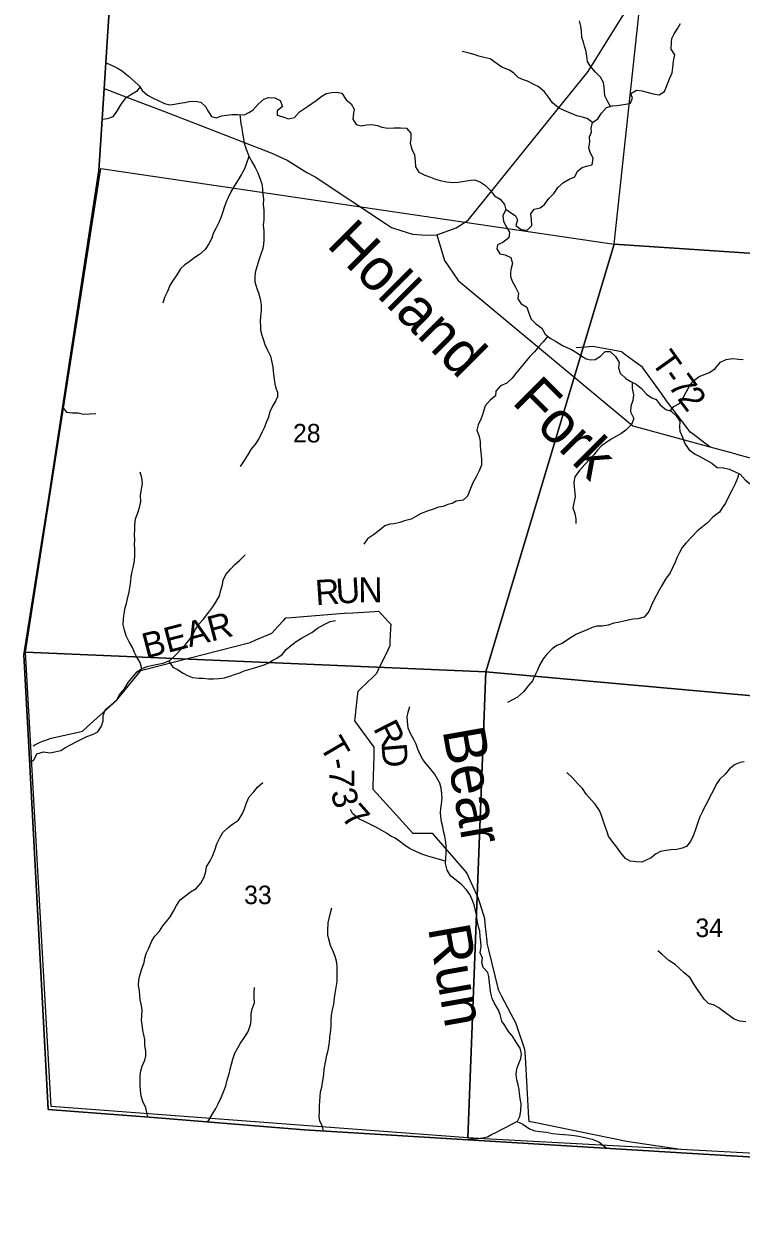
# Model space of a CAD drawing. Extents: x 1715311 to 2083412, y 146837 to 553079.
# Drawn here: x 1893959 to 1902515, y 310262 to 324418 of the extents above; entities that cross this region are included whole.
import ezdxf

# ---------------------------------------------------------------- set-up
doc = ezdxf.new("R2010")
doc.units = 0
for name, color, linetype in [('GM_X_Adjacent_County', 7, 'Continuous'), ('GM_X_County', 7, 'Continuous'), ('GM_X_Minor_River', 7, 'Continuous'), ('GM_X_Minor_River_Text', 7, 'Continuous'), ('GM_X_Section', 7, 'Continuous'), ('GM_X_Section_Text', 7, 'Continuous'), ('GM_X_State_Route', 7, 'Continuous'), ('GM_X_Township', 7, 'Continuous'), ('GM_X_Township_Road', 7, 'Continuous'), ('GM_X_Township_Road_Text', 7, 'Continuous')]:
    doc.layers.add(name, color=color, linetype=linetype)

msp = doc.modelspace()

# ---------------------------------------------------------------- linework, layer by layer
at = {"layer": 'GM_X_Adjacent_County'}
msp.add_lwpolyline([(1896008, 339458), (1895779, 336659), (1895744, 336194), (1895699, 335683), (1895663, 335244), (1895523, 333111), (1895188, 327845), (1894919, 323647), (1894856, 322668), (1894263, 318800), (1893959, 316894), (1894019, 315798), (1894252, 311474), (1895508, 311379), (1897304, 311233), (1901800, 310959), (1903135, 310878), (1905084, 310759), (1910567, 310425), (1912652, 310262)], dxfattribs=at)
at = {"layer": 'GM_X_County'}
msp.add_lwpolyline([(1912652, 310262), (1910567, 310425), (1905084, 310759), (1903135, 310878), (1901800, 310959), (1897304, 311233), (1895508, 311379), (1894252, 311474), (1894019, 315798), (1893959, 316894), (1894263, 318800), (1894856, 322668), (1894919, 323647), (1895188, 327845), (1895523, 333111), (1895663, 335244), (1895699, 335683), (1895744, 336194), (1895779, 336659), (1896008, 339458)], dxfattribs=at)
at = {"layer": 'GM_X_Minor_River'}
for points in [[(1900957, 323433), (1900924, 323486), (1900888, 323558), (1900886, 323610), (1900880, 323662), (1900871, 323716), (1900837, 323783), (1900777, 323839), (1900713, 323917), (1900682, 323967), (1900672, 324031), (1900664, 324088), (1900644, 324150), (1900633, 324200), (1900615, 324252), (1900609, 324330), (1900603, 324388), (1900588, 324452)], [(1899706, 322208), (1899748, 322178), (1899822, 322129), (1899846, 322079), (1899828, 322011), (1899891, 321967), (1899963, 321957), (1900017, 322011), (1900014, 322085), (1900004, 322153), (1900044, 322209), (1900118, 322224), (1900168, 322264), (1900222, 322336), (1900284, 322400), (1900327, 322464), (1900395, 322527), (1900463, 322565), (1900529, 322595), (1900563, 322659), (1900617, 322705), (1900669, 322721), (1900737, 322736), (1900751, 322816), (1900714, 322883), (1900698, 322939), (1900710, 323005), (1900704, 323069), (1900731, 323125), (1900725, 323175), (1900743, 323241), (1900805, 323286), (1900847, 323350), (1900907, 323418), (1900979, 323440), (1901031, 323442), (1901087, 323451), (1901139, 323459), (1901195, 323473), (1901217, 323531), (1901198, 323585), (1901264, 323627), (1901332, 323619), (1901389, 323602), (1901465, 323582), (1901535, 323570), (1901601, 323610), (1901633, 323688), (1901658, 323760), (1901690, 323831), (1901698, 323895), (1901708, 323973), (1901721, 324049), (1901681, 324116), (1901685, 324194), (1901689, 324244), (1901716, 324296), (1901758, 324366), (1901790, 324419)], [(1900743, 323240), (1900677, 323287), (1900607, 323309), (1900555, 323321), (1900478, 323352), (1900402, 323382), (1900334, 323414), (1900264, 323475), (1900217, 323543), (1900167, 323605), (1900095, 323669), (1900042, 323694), (1899968, 323732), (1899908, 323754), (1899856, 323778), (1899802, 323827), (1899751, 323863), (1899661, 323899), (1899593, 323948), (1899521, 323998), (1899449, 324014), (1899386, 324032), (1899330, 324053), (1899254, 324073), (1899188, 324087)], [(1894942, 323953), (1895023, 323917), (1895085, 323883), (1895137, 323853), (1895209, 323793), (1895276, 323732), (1895340, 323674), (1895370, 323622), (1895434, 323568), (1895504, 323529), (1895555, 323505), (1895639, 323469), (1895701, 323453), (1895757, 323458), (1895819, 323470), (1895875, 323480), (1895933, 323490), (1896003, 323496), (1896071, 323485), (1896125, 323433), (1896162, 323367), (1896198, 323313), (1896252, 323295), (1896322, 323320), (1896378, 323330), (1896442, 323336), (1896510, 323338), (1896590, 323331), (1896644, 323361), (1896694, 323393), (1896756, 323459), (1896824, 323519), (1896877, 323537), (1896952, 323536), (1897016, 323504), (1897046, 323432), (1896980, 323380), (1896982, 323330), (1897050, 323310), (1897117, 323286), (1897189, 323301), (1897246, 323369), (1897342, 323430)], [(1895346, 323664), (1895302, 323612), (1895236, 323570), (1895166, 323523), (1895112, 323453), (1895073, 323383), (1895021, 323309), (1894953, 323283), (1894899, 323277)], [(1897342, 323430), (1897446, 323504), (1897512, 323555), (1897564, 323587), (1897634, 323599), (1897688, 323601), (1897754, 323592), (1897802, 323512), (1897863, 323464), (1897901, 323400), (1897893, 323350), (1897885, 323282), (1897924, 323217), (1897982, 323199), (1898046, 323211), (1898108, 323217), (1898176, 323204), (1898228, 323184), (1898302, 323172), (1898378, 323178), (1898452, 323179), (1898522, 323175), (1898573, 323115), (1898575, 323047), (1898569, 322995), (1898587, 322921), (1898618, 322857), (1898628, 322780), (1898630, 322712), (1898671, 322648), (1898743, 322612), (1898809, 322588), (1898869, 322565), (1898925, 322549), (1898999, 322535), (1899076, 322525), (1899140, 322528), (1899216, 322542), (1899286, 322554), (1899340, 322558), (1899406, 322531), (1899464, 322489), (1899524, 322431), (1899573, 322365), (1899639, 322326), (1899693, 322264), (1899708, 322200), (1899670, 322134), (1899678, 322062), (1899714, 321994), (1899751, 321934), (1899745, 321866), (1899673, 321812), (1899609, 321784), (1899601, 321734), (1899635, 321674), (1899698, 321662), (1899766, 321631), (1899786, 321561), (1899772, 321505), (1899764, 321455), (1899765, 321403), (1899785, 321349), (1899821, 321277), (1899857, 321207), (1899850, 321137), (1899892, 321078), (1899958, 321040), (1899980, 320968), (1900011, 320896), (1900067, 320842), (1900137, 320789), (1900176, 320719), (1900238, 320671), (1900300, 320635), (1900384, 320584), (1900435, 320560), (1900491, 320536), (1900561, 320491), (1900613, 320455), (1900667, 320423), (1900721, 320413), (1900774, 320417), (1900835, 320454), (1900893, 320512), (1900953, 320512), (1901016, 320452), (1901060, 320381), (1901050, 320317), (1901069, 320253), (1901137, 320191), (1901189, 320157), (1901263, 320120), (1901326, 320068), (1901384, 320004), (1901450, 319960), (1901502, 319937), (1901547, 319875), (1901615, 319819), (1901681, 319801), (1901739, 319746)], [(1896537, 323336), (1896548, 323225), (1896561, 323173), (1896569, 323109), (1896579, 323045), (1896589, 322993), (1896611, 322921), (1896638, 322851), (1896674, 322779), (1896718, 322706), (1896751, 322640), (1896779, 322566), (1896797, 322510), (1896807, 322446), (1896812, 322388), (1896818, 322328), (1896816, 322262), (1896822, 322194), (1896821, 322081), (1896815, 322015), (1896823, 321947), (1896823, 321841), (1896820, 321791), (1896810, 321739), (1896784, 321659), (1896758, 321589), (1896744, 321531), (1896723, 321467), (1896713, 321411), (1896713, 321341), (1896739, 321261), (1896758, 321211), (1896778, 321137), (1896790, 321069), (1896790, 320994), (1896783, 320934), (1896779, 320866), (1896781, 320814), (1896783, 320764), (1896799, 320706), (1896818, 320646), (1896834, 320596), (1896866, 320528), (1896900, 320456), (1896915, 320400), (1896929, 320329), (1896935, 320277), (1896947, 320177), (1896952, 320125), (1896966, 320075), (1896986, 320025), (1896984, 319969), (1896960, 319917), (1896925, 319861), (1896895, 319791), (1896875, 319717), (1896851, 319665), (1896831, 319609), (1896804, 319553), (1896766, 319479), (1896724, 319411), (1896668, 319341), (1896626, 319277), (1896587, 319212), (1896541, 319142)], [(1896645, 322837), (1896610, 322745), (1896590, 322689), (1896552, 322617), (1896515, 322559), (1896469, 322483), (1896425, 322405), (1896395, 322345), (1896370, 322285), (1896348, 322229), (1896332, 322175), (1896312, 322117), (1896286, 322047), (1896252, 321987), (1896219, 321919), (1896201, 321861), (1896165, 321793), (1896123, 321726), (1896055, 321666), (1895998, 321630), (1895932, 321580), (1895880, 321546), (1895828, 321496), (1895786, 321424), (1895734, 321351), (1895703, 321297), (1895675, 321227), (1895639, 321155), (1895617, 321089)], [(1900207, 320695), (1900154, 320627), (1900098, 320567), (1900048, 320507), (1899988, 320446), (1899933, 320378), (1899877, 320314), (1899835, 320262), (1899783, 320194), (1899719, 320132), (1899643, 320103), (1899589, 320037), (1899584, 319981), (1899520, 319929), (1899462, 319865), (1899444, 319813), (1899430, 319755), (1899410, 319703), (1899379, 319635), (1899363, 319573), (1899391, 319499), (1899403, 319437), (1899402, 319383), (1899408, 319305), (1899416, 319229), (1899416, 319157), (1899389, 319089), (1899355, 319017), (1899315, 318947), (1899285, 318879), (1899251, 318785)], [(1901666, 319805), (1901709, 319857), (1901777, 319892), (1901823, 319960), (1901862, 320034), (1901900, 320104), (1901948, 320166), (1902014, 320214), (1902086, 320239), (1902138, 320259), (1902202, 320307), (1902266, 320383), (1902334, 320417), (1902410, 320428), (1902484, 320420), (1902538, 320416)], [(1901213, 320145), (1901215, 320075), (1901230, 319994), (1901222, 319928), (1901200, 319860), (1901196, 319792), (1901235, 319712), (1901205, 319642), (1901139, 319573), (1901079, 319529), (1901027, 319503), (1900963, 319465), (1900899, 319421), (1900849, 319386), (1900796, 319332), (1900758, 319278), (1900708, 319226), (1900650, 319164), (1900586, 319094), (1900530, 319018), (1900519, 318952), (1900521, 318898), (1900535, 318783)], [(1894426, 319842), (1894469, 319789), (1894539, 319779), (1894607, 319781), (1894673, 319765), (1894743, 319768), (1894819, 319770)], [(1901739, 319746), (1901782, 319680), (1901780, 319610), (1901782, 319560), (1901810, 319496), (1901845, 319408), (1901893, 319337), (1901965, 319289), (1902021, 319261), (1902092, 319221), (1902162, 319180), (1902226, 319130), (1902302, 319124), (1902370, 319109), (1902435, 319079), (1902501, 319047), (1902561, 318981), (1902627, 318928), (1902678, 318898), (1902752, 318868), (1902818, 318850), (1902886, 318829), (1902987, 318778)], [(1895353, 318796), (1895365, 318869), (1895375, 318936), (1895368, 319006), (1895346, 319074)], [(1902486, 319054), (1902469, 319001), (1902443, 318933), (1902405, 318861), (1902363, 318779)], [(1895366, 316730), (1895349, 316805), (1895307, 316869), (1895279, 316921), (1895256, 316983), (1895216, 317050), (1895182, 317120), (1895160, 317188), (1895145, 317252), (1895147, 317324), (1895157, 317388), (1895169, 317454), (1895186, 317506), (1895198, 317562), (1895216, 317648), (1895230, 317718), (1895237, 317772), (1895241, 317822), (1895249, 317872), (1895265, 317938), (1895280, 318015), (1895286, 318085), (1895284, 318159), (1895282, 318211), (1895283, 318271), (1895281, 318321), (1895285, 318389), (1895285, 318441), (1895293, 318515), (1895318, 318587), (1895340, 318651), (1895355, 318723), (1895353, 318796)], [(1899251, 318785), (1899199, 318740), (1899116, 318725), (1899066, 318701), (1899016, 318686), (1898962, 318664), (1898906, 318654), (1898834, 318628), (1898782, 318612), (1898700, 318580), (1898636, 318545), (1898578, 318513), (1898500, 318493), (1898442, 318473), (1898376, 318457), (1898324, 318451), (1898266, 318434), (1898197, 318376), (1898131, 318326), (1898057, 318276), (1898013, 318216)], [(1900535, 318783), (1900507, 318649), (1900532, 318581), (1900544, 318515), (1900542, 318461)], [(1902363, 318779), (1902325, 318702), (1902289, 318646), (1902255, 318594), (1902177, 318536), (1902113, 318470), (1902053, 318420), (1901995, 318372), (1901924, 318300), (1901854, 318226), (1901812, 318173), (1901778, 318113), (1901752, 318059), (1901726, 318001), (1901691, 317925), (1901667, 317873), (1901611, 317797), (1901567, 317721), (1901537, 317665), (1901505, 317607), (1901476, 317553), (1901444, 317487), (1901412, 317413), (1901356, 317345), (1901282, 317325), (1901224, 317319), (1901168, 317308), (1901116, 317296), (1901048, 317280), (1900994, 317272), (1900926, 317250), (1900856, 317238), (1900792, 317235), (1900738, 317219), (1900684, 317199), (1900618, 317169), (1900552, 317141), (1900480, 317099), (1900380, 317032), (1900316, 317008), (1900260, 316968), (1900197, 316904), (1900151, 316848), (1900109, 316770), (1900087, 316714), (1900053, 316650), (1900027, 316584), (1899974, 316526), (1899918, 316456), (1899848, 316392), (1899786, 316359), (1899726, 316327)], [(1894032, 315615), (1894078, 315639), (1894116, 315713), (1894197, 315737), (1894271, 315728), (1894331, 315738), (1894401, 315756), (1894451, 315785), (1894525, 315825), (1894593, 315861), (1894649, 315889), (1894711, 315922), (1894779, 315944), (1894844, 315978), (1894888, 316046), (1894906, 316108), (1894906, 316172), (1894933, 316242), (1895001, 316298), (1895069, 316357), (1895105, 316431), (1895164, 316499), (1895206, 316565), (1895264, 316635), (1895312, 316693), (1895367, 316731), (1895433, 316756), (1895499, 316772), (1895579, 316786), (1895633, 316799), (1895707, 316833), (1895765, 316887), (1895836, 316961), (1895890, 317019), (1895944, 317086), (1895974, 317138), (1896009, 317196), (1896049, 317262), (1896099, 317318), (1896165, 317402), (1896216, 317468), (1896250, 317522), (1896292, 317598), (1896310, 317666), (1896331, 317732), (1896339, 317784), (1896369, 317853), (1896425, 317917), (1896472, 317969), (1896536, 318023), (1896600, 318087)], [(1897324, 317123), (1897396, 317163), (1897462, 317213), (1897542, 317258), (1897614, 317292), (1897676, 317304)], [(1895687, 316824), (1895739, 316747), (1895793, 316721), (1895860, 316678), (1895914, 316650), (1895970, 316624), (1896046, 316615), (1896098, 316615), (1896162, 316609), (1896224, 316609), (1896286, 316612), (1896354, 316622), (1896418, 316642), (1896483, 316664), (1896537, 316679), (1896589, 316703), (1896643, 316721), (1896699, 316735), (1896825, 316776), (1896877, 316800), (1896929, 316830), (1896979, 316856), (1897042, 316899), (1897088, 316959), (1897156, 317015), (1897208, 317053), (1897272, 317093), (1897324, 317123)], [(1899841, 311330), (1899875, 311393), (1899887, 311461), (1899889, 311541), (1899879, 311605), (1899871, 311665), (1899868, 311715), (1899856, 311771), (1899838, 311829), (1899830, 311893), (1899840, 311961), (1899861, 312025), (1899885, 312085), (1899895, 312135), (1899877, 312206), (1899829, 312278), (1899788, 312350), (1899740, 312404), (1899694, 312476), (1899662, 312527), (1899640, 312607), (1899619, 312661), (1899569, 312747), (1899545, 312799), (1899529, 312863), (1899522, 312919), (1899512, 312988), (1899504, 313060), (1899492, 313110), (1899436, 313166), (1899423, 313228), (1899429, 313278), (1899403, 313342), (1899415, 313420), (1899409, 313470), (1899402, 313536), (1899396, 313601), (1899382, 313653), (1899366, 313727), (1899358, 313795), (1899347, 313849), (1899329, 313915), (1899311, 313967), (1899279, 314037), (1899239, 314092), (1899184, 314154), (1899120, 314206), (1899052, 314258), (1899010, 314329), (1898989, 314407), (1898991, 314467), (1898997, 314537), (1898995, 314611), (1898993, 314661), (1898982, 314733), (1898964, 314793), (1898956, 314845), (1898942, 314903), (1898932, 314962), (1898930, 315014), (1898933, 315064), (1898941, 315116), (1898949, 315190), (1898943, 315240), (1898935, 315304), (1898920, 315364), (1898888, 315422), (1898856, 315476), (1898804, 315539), (1898756, 315595), (1898719, 315647), (1898689, 315701), (1898659, 315771), (1898637, 315829), (1898611, 315884), (1898572, 315958), (1898544, 316020), (1898534, 316106), (1898532, 316156), (1898542, 316210), (1898563, 316278)], [(1902550, 315621), (1902500, 315610), (1902442, 315586), (1902376, 315536), (1902321, 315472), (1902257, 315410), (1902221, 315358), (1902183, 315280), (1902137, 315196), (1902109, 315136), (1902078, 315080), (1902054, 315028), (1902022, 314964), (1902000, 314910), (1901982, 314850), (1901962, 314788), (1901943, 314736), (1901911, 314668), (1901863, 314610), (1901811, 314590), (1901747, 314575), (1901677, 314569), (1901621, 314563), (1901553, 314549), (1901491, 314517), (1901439, 314477), (1901389, 314452), (1901329, 314424), (1901261, 314426), (1901189, 314436), (1901135, 314468), (1901079, 314533), (1901032, 314603), (1900982, 314663), (1900932, 314735), (1900916, 314785), (1900893, 314847), (1900871, 314908), (1900849, 314980), (1900825, 315040), (1900771, 315116), (1900726, 315166), (1900666, 315235), (1900622, 315303), (1900572, 315355), (1900503, 315427), (1900435, 315494)], [(1895439, 311385), (1895416, 311494), (1895381, 311572), (1895359, 311636), (1895353, 311704), (1895349, 311761), (1895348, 311815), (1895348, 311879), (1895354, 311937), (1895370, 311993), (1895403, 312063), (1895415, 312115), (1895417, 312167), (1895405, 312241), (1895402, 312309), (1895390, 312367), (1895378, 312421), (1895370, 312489), (1895364, 312539), (1895367, 312591), (1895371, 312658), (1895365, 312714), (1895349, 312784), (1895342, 312834), (1895338, 312888), (1895328, 312954), (1895332, 313020), (1895343, 313072), (1895365, 313142), (1895397, 313226), (1895405, 313278), (1895420, 313334), (1895452, 313400), (1895488, 313484), (1895524, 313540), (1895577, 313600), (1895619, 313666), (1895661, 313718), (1895705, 313773), (1895744, 313841), (1895782, 313907), (1895826, 313975), (1895892, 314027), (1895948, 314069), (1896015, 314110), (1896071, 314174), (1896111, 314244), (1896131, 314312), (1896138, 314368), (1896182, 314440), (1896212, 314496), (1896236, 314566), (1896263, 314642), (1896303, 314720), (1896333, 314778), (1896395, 314838), (1896450, 314875), (1896520, 314923), (1896562, 314995), (1896590, 315059), (1896615, 315131), (1896647, 315203), (1896701, 315263), (1896745, 315319), (1896810, 315372)], [(1898990, 314436), (1898887, 314463), (1898835, 314479), (1898779, 314497), (1898705, 314520), (1898627, 314554), (1898561, 314586), (1898494, 314632), (1898442, 314669), (1898388, 314709), (1898336, 314735), (1898284, 314769), (1898230, 314803), (1898164, 314836), (1898103, 314870), (1898029, 314906), (1897953, 314942), (1897881, 315003), (1897857, 315053)], [(1897532, 311220), (1897516, 311286), (1897490, 311336), (1897482, 311394), (1897484, 311446), (1897485, 311520), (1897489, 311576), (1897495, 311630), (1897499, 311686), (1897513, 311742), (1897523, 311798), (1897538, 311890), (1897542, 311956), (1897560, 312058), (1897572, 312124), (1897591, 312184), (1897605, 312274), (1897611, 312338), (1897619, 312391), (1897625, 312465), (1897626, 312533), (1897630, 312601), (1897640, 312663), (1897656, 312731), (1897665, 312807), (1897671, 312859), (1897685, 312931), (1897697, 313003), (1897697, 313123), (1897698, 313189), (1897690, 313243), (1897672, 313299), (1897652, 313352), (1897618, 313430), (1897597, 313504), (1897587, 313556), (1897585, 313610), (1897589, 313700), (1897601, 313752), (1897612, 313804), (1897632, 313880)], [(1902568, 312522), (1902498, 312528), (1902432, 312554), (1902370, 312596), (1902301, 312649), (1902249, 312689), (1902191, 312717), (1902125, 312737), (1902073, 312790), (1902028, 312856), (1901992, 312906), (1901946, 312978), (1901904, 313046), (1901836, 313105), (1901777, 313157), (1901725, 313205), (1901653, 313253), (1901573, 313322), (1901521, 313368)], [(1896153, 311328), (1896206, 311414), (1896249, 311486), (1896279, 311544), (1896315, 311618), (1896343, 311684), (1896368, 311756), (1896390, 311842), (1896410, 311900), (1896422, 311958), (1896435, 312014), (1896453, 312074), (1896475, 312146), (1896511, 312212), (1896544, 312266), (1896586, 312330), (1896632, 312396), (1896652, 312450), (1896667, 312502), (1896673, 312558), (1896671, 312616), (1896685, 312674), (1896711, 312746), (1896708, 312818), (1896706, 312868), (1896710, 312930)], [(1899199, 311119), (1899296, 311126), (1899366, 311130), (1899434, 311136), (1899488, 311151), (1899538, 311177), (1899598, 311205), (1899648, 311233), (1899718, 311269), (1899770, 311297), (1899838, 311331), (1899912, 311302), (1899988, 311246), (1900054, 311220), (1900112, 311214), (1900194, 311205), (1900266, 311191), (1900348, 311181), (1900401, 311177), (1900455, 311175), (1900521, 311166), (1900577, 311156), (1900631, 311146), (1900687, 311132), (1900739, 311122), (1900815, 311091), (1900912, 311014)]]:
    msp.add_lwpolyline(points, dxfattribs=at)
at = {"layer": 'GM_X_Section'}
for points in [[(1901579, 327188), (1902559, 327082), (1905895, 327025), (1905532, 321487), (1901000, 321792)], [(1894878, 322694), (1901000, 321792), (1899470, 316693), (1893982, 316925)], [(1905532, 321487), (1905032, 316191), (1899470, 316693), (1901000, 321792)], [(1893982, 316925), (1899470, 316693), (1899255, 311137), (1894286, 311510)], [(1899470, 316693), (1905032, 316191), (1904807, 310836), (1899451, 311126), (1899255, 311137)]]:
    msp.add_lwpolyline(points, close=True, dxfattribs=at)
at = {"layer": 'GM_X_State_Route'}
for points in [[(1898885, 321902), (1899117, 321984), (1899257, 322077), (1900319, 323391), (1900689, 323849), (1900996, 324342), (1901468, 325099)], [(1894919, 323647), (1895198, 323538), (1895587, 323391), (1896009, 323230), (1896509, 323036), (1896916, 322877), (1897099, 322791), (1897333, 322646), (1897435, 322592), (1898272, 322038), (1898344, 321991), (1898544, 321925), (1898595, 321908), (1898701, 321902), (1898783, 321896), (1898885, 321902)], [(1898885, 321902), (1898975, 321594), (1899138, 321358), (1901222, 319623), (1902141, 319375), (1902440, 319294)], [(1902440, 319294), (1902457, 319289), (1903711, 318951)]]:
    msp.add_lwpolyline(points, dxfattribs=at)
at = {"layer": 'GM_X_Township'}
msp.add_lwpolyline([(1912652, 310262), (1910567, 310425), (1905084, 310759), (1903135, 310878), (1901800, 310959), (1897304, 311233), (1895508, 311379), (1894252, 311474), (1894019, 315798), (1893959, 316894), (1894263, 318800), (1894856, 322668), (1894919, 323647), (1895188, 327845), (1895523, 333111), (1895663, 335244), (1895699, 335683), (1895744, 336194), (1895779, 336659), (1896008, 339458)], dxfattribs=at)
at = {"layer": 'GM_X_Township_Road'}
for points in [[(1902141, 319375), (1902096, 319408), (1901924, 319538), (1901906, 319551), (1901854, 319620), (1901625, 319921), (1901624, 319922), (1901563, 320009), (1901343, 320317), (1901340, 320322), (1901257, 320381), (1901126, 320477), (1901085, 320506), (1901029, 320517), (1900763, 320568), (1900739, 320572), (1900656, 320564), (1900602, 320559), (1900548, 320554)], [(1894072, 315811), (1894092, 315824), (1894131, 315844), (1894184, 315866), (1894221, 315879), (1894287, 315900), (1894630, 315978), (1894659, 315985), (1894715, 316035), (1895026, 316313), (1895063, 316346), (1895098, 316389), (1895328, 316674), (1895357, 316709), (1895414, 316724), (1896628, 317036), (1896658, 317044), (1896726, 317073), (1896918, 317154), (1896918, 317154), (1896989, 317231), (1897060, 317308), (1897084, 317335), (1897152, 317340), (1897778, 317391), (1897784, 317391), (1897882, 317397), (1898143, 317412), (1898190, 317415), (1898229, 317374), (1898301, 317298), (1898336, 317261), (1898334, 317207), (1898326, 317050), (1898324, 317004), (1898299, 316952), (1898187, 316716), (1898166, 316673), (1898125, 316633), (1897974, 316489), (1897942, 316458), (1897935, 316398), (1897906, 316139), (1897902, 316109), (1897946, 316049), (1898132, 315796), (1898134, 315792), (1898132, 315692), (1898123, 315326), (1898122, 315295), (1898171, 315241), (1898592, 314776), (1898596, 314771), (1898830, 314771), (1898878, 314715), (1899218, 314319), (1899246, 314286), (1899271, 314230), (1899357, 314039), (1899374, 314003), (1899393, 313941), (1899440, 313792), (1899452, 313752), (1899458, 313689), (1899480, 313481), (1899482, 313460), (1899501, 313379), (1899613, 312922), (1899620, 312896), (1899656, 312828), (1899803, 312550), (1899824, 312511), (1899843, 312454), (1899927, 312207), (1899932, 312194), (1899937, 312103), (1899978, 311373), (1899980, 311337), (1900047, 311323), (1901071, 311113), (1901101, 311107), (1901174, 311092), (1901792, 311002)]]:
    msp.add_lwpolyline(points, dxfattribs=at)

# ---------------------------------------------------------------- texts
at = {"layer": 'GM_X_Minor_River_Text'}
for s, rotation, p in [('Holland', 314.9962, (1897558, 321772)), ('Fork', 314.9962, (1899769, 319900)), ('Bear', 279.9993, (1898952, 315995)), ('Run', 279.999, (1898778, 313640))]:
    msp.add_text(s, height=500, rotation=rotation, dxfattribs=at).set_placement(p)
at = {"layer": 'GM_X_Section_Text'}
for s, p in [('28', (1897170, 319427)), ('33', (1896587, 313923)), ('34', (1901968, 313531))]:
    msp.add_text(s, height=221, rotation=0, dxfattribs=at).set_placement(p)
at = {"layer": 'GM_X_Township_Road_Text'}
for s, rotation, p in [('T', 305.4786, (1901431, 320388)), ('-', 305.4679, (1901561, 320206)), ('7', 305.8955, (1901633, 320104)), ('2', 307.3004, (1901745, 319949)), ('R', 3.7183, (1897444, 317486)), ('U', 3.7109, (1897690, 317502)), ('N', 0.2769, (1897949, 317519)), ('BEAR', 14.5991, (1895417, 316849)), ('R', 296.8583, (1898121, 316019)), ('T', 300.3434, (1897478, 315809)), ('D', 274.8323, (1898224, 315829)), ('-', 280.7098, (1897582, 315640)), ('7', 269.8022, (1897603, 315534)), ('3', 285.8163, (1897615, 315259)), ('7', 311.5953, (1897735, 314953))]:
    msp.add_text(s, height=300, rotation=rotation, dxfattribs=at).set_placement(p)

doc.saveas('drawing.dxf')
